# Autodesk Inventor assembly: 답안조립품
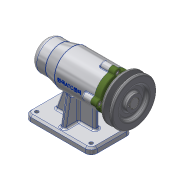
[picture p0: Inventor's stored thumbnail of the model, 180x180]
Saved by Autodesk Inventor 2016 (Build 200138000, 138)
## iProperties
Created: 2019-07
Part Number: 답안조립품
Material: 일반
Document SubType Name: Assembly
Designer: 605-17
Author: 605-17
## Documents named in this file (11)
- C:\Users\605-17\Desktop\490704V1061\답안조립품.iam
- C:\Users\605-17\Desktop\490704V1061\본체.ipt
- C:\Users\605-17\Desktop\490704V1061\축.ipt
- C:\Users\605-17\Desktop\490704V1061\베어링 6004.ipt
- C:\Users\605-17\Desktop\490704V1061\어댑터슬리브.ipt
- C:\Users\605-17\Desktop\490704V1061\볼트 M4.ipt
- C:\Users\605-17\Desktop\490704V1061\베어링 51202.ipt
- C:\Users\605-17\Desktop\490704V1061\커버.ipt
- C:\Users\605-17\Desktop\490704V1061\키 5 x 5 x 16.ipt
- C:\Users\605-17\Desktop\490704V1061\V벨트풀리.ipt
- C:\Users\605-17\Desktop\490704V1061\멈춤나사 M3.ipt
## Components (1 placed, 1 different names)
1. V벨트풀리:1 — 각도:2
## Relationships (1: Angle 1)
- 각도:2 [Angle]: V벨트풀리:1
